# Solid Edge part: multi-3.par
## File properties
Author: CADCIM
Template: Iso Part.par
Last saved by: Cadcim
Revision: 3
Application: Solid Edge
Accuracy: 0.990
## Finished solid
Body 1: solid body, 3 faces, 2 edges, 0 vertices.
  Faces by surface: plane 2, cylinder 1
  Edges by curve: circle 2
Bounding box of the edges (mm): 100.000 x 100.000 x 35.000, from (-50, -50, 0) to (50, 50, 35).
Cylindrical faces by radius (mm): R50 x1
Planar faces by outward normal: +z 1, -z 1
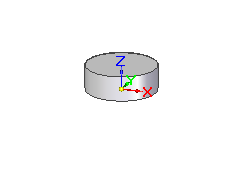
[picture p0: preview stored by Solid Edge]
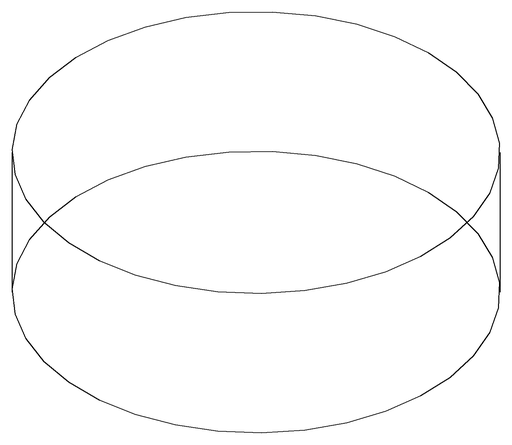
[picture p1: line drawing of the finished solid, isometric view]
